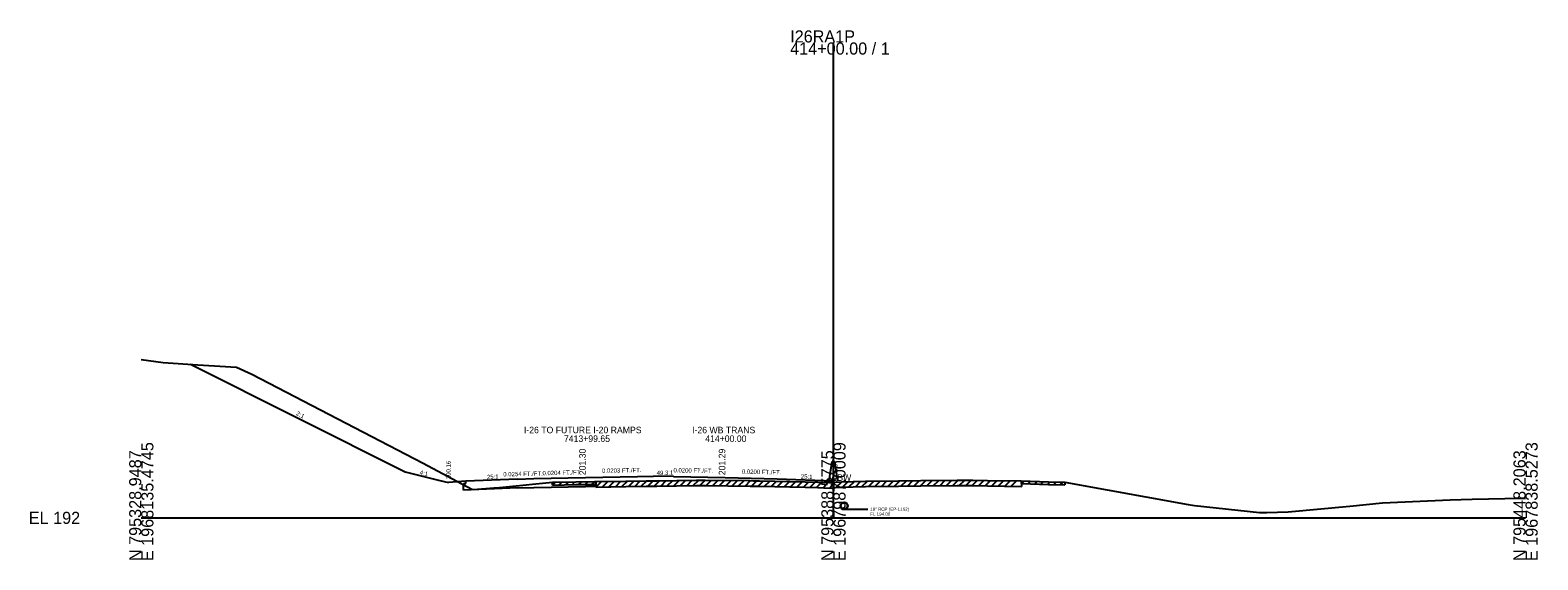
# Model space of a CAD drawing. Extents: x -44 to 4323, y -10 to 9601.
# Drawn here: x -25.7 to 322.8, y 8490.3 to 8612.7 of the extents above; entities that cross this region are included whole.
import ezdxf

# ---------------------------------------------------------------- set-up
doc = ezdxf.new("R2010")
doc.units = 0
for name, color, linetype in [('1', 7, 'Continuous'), ('DateStamp', 7, 'Continuous'), ('NotForConst', 7, 'Continuous'), ('QCQA', 7, 'Continuous'), ('RD_SHT_Bndy', 7, 'Continuous'), ('RD_SHT_Iplotshp', 7, 'Continuous'), ('RD_SHT_TX', 7, 'Continuous'), ('RD_TX_Misc1', 7, 'Continuous'), ('RD_XS_ExGround', 7, 'Continuous'), ('RD_XS_Misc_Line', 7, 'Continuous'), ('RD_XS_Pave', 7, 'Continuous'), ('RD_XS_PaveShd', 7, 'Continuous'), ('RD_XS_Pipe', 7, 'Continuous'), ('RD_XS_TX_Elev_PR', 7, 'Continuous'), ('RD_XS_TX_Profile', 7, 'Continuous'), ('RD_XS_TX_ShdSlope', 7, 'Continuous'), ('RD_XS_TX_Slope', 7, 'Continuous'), ('seal', 7, 'Continuous'), ('TR SN EXTRUDED PANEL SIGNS - GROUND MOUNTED', 7, 'Continuous')]:
    doc.layers.add(name, color=color, linetype=linetype)

msp = doc.modelspace()

# ---------------------------------------------------------------- linework, layer by layer
at = {"layer": 'DateStamp'}
msp.add_lwpolyline([(0, 8536.6), (5.07, 8535.9), (13.06, 8535.36), (22, 8534.83), (25.55, 8533.16), (65.15, 8512.65), (76.4, 8506.64), (76.79, 8506.54), (81.49, 8506.92), (82.06, 8506.96), (84.32, 8507.18), (95.09, 8508.22), (100.47, 8508.3), (104.77, 8508.37), (112.01, 8508.48), (116.68, 8508.56), (119.15, 8508.59), (128.37, 8508.7), (130.34, 8508.71), (140.72, 8508.6), (141.56, 8508.59), (142.89, 8508.56), (153.47, 8508.35), (156.37, 8508.25), (159.12, 8508.14), (160, 8508.2), (160.47, 8508.23), (161.85, 8508.33), (164.57, 8508.41), (167.42, 8508.48), (175.03, 8508.56), (180.19, 8508.63), (188.59, 8508.69), (192.22, 8508.72), (195.62, 8508.65), (203.37, 8508.52), (209.7, 8508.36), (213.46, 8508.27), (242.01, 8503.1), (242.98, 8502.93), (243.47, 8502.86), (258.51, 8501.23), (260.16, 8501.27), (265.13, 8501.43), (279.36, 8502.68), (286.9, 8503.49), (302.57, 8504.16), (307.63, 8504.33), (318.98, 8504.54), (320, 8504.54)], dxfattribs=at)
at = {"layer": 'NotForConst'}
for p, q in [((95.09, 8507.59), (95.73, 8508.23)), ((96.59, 8507.62), (97.23, 8508.25)), ((98.09, 8507.64), (98.73, 8508.27)), ((99.59, 8507.66), (100.23, 8508.3)), ((101.09, 8507.69), (101.73, 8508.32)), ((102.59, 8507.71), (103.23, 8508.34)), ((104.09, 8507.73), (104.73, 8508.36)), ((105.09, 8507.12), (106.36, 8508.39)), ((106.59, 8507.14), (107.86, 8508.41)), ((108.09, 8507.17), (109.36, 8508.44)), ((109.59, 8507.19), (110.86, 8508.46)), ((111.09, 8507.21), (112.36, 8508.49)), ((112.59, 8507.24), (113.86, 8508.51)), ((114.09, 8507.26), (115.36, 8508.54)), ((115.59, 8507.29), (116.86, 8508.56)), ((117.09, 8507.31), (118.36, 8508.58)), ((118.59, 8507.33), (119.86, 8508.6)), ((120.09, 8507.35), (121.36, 8508.62)), ((121.59, 8507.37), (122.86, 8508.63)), ((123.09, 8507.39), (124.36, 8508.65)), ((124.59, 8507.4), (125.86, 8508.67)), ((126.09, 8507.42), (127.36, 8508.69)), ((127.59, 8507.44), (128.86, 8508.7)), ((129.09, 8507.45), (130.35, 8508.71)), ((130.59, 8507.46), (131.83, 8508.7)), ((132.09, 8507.44), (133.33, 8508.68)), ((133.59, 8507.43), (134.83, 8508.66)), ((135.09, 8507.41), (136.33, 8508.65)), ((136.59, 8507.39), (137.83, 8508.63)), ((138.09, 8507.38), (139.33, 8508.61)), ((139.59, 8507.36), (140.83, 8508.6)), ((141.09, 8507.34), (142.32, 8508.57)), ((142.59, 8507.32), (143.82, 8508.54)), ((144.09, 8507.29), (145.32, 8508.51)), ((145.59, 8507.26), (146.82, 8508.48)), ((147.09, 8507.23), (148.32, 8508.45)), ((148.59, 8507.2), (149.82, 8508.42)), ((150.09, 8507.17), (151.32, 8508.4)), ((151.59, 8507.14), (152.82, 8508.37)), ((153.09, 8507.11), (154.31, 8508.32)), ((154.59, 8507.06), (155.8, 8508.27)), ((156.09, 8507.01), (157.3, 8508.21)), ((157.59, 8506.95), (158.8, 8508.16)), ((159.09, 8506.89), (160.43, 8508.23)), ((160.59, 8506.99), (161.94, 8508.34)), ((162.09, 8507.09), (163.38, 8508.38)), ((163.59, 8507.13), (164.88, 8508.42)), ((165.09, 8507.17), (166.37, 8508.45)), ((166.59, 8507.21), (167.87, 8508.48)), ((168.09, 8507.24), (169.36, 8508.5)), ((169.59, 8507.25), (170.86, 8508.52)), ((171.09, 8507.27), (172.36, 8508.53)), ((172.59, 8507.28), (173.86, 8508.55)), ((174.09, 8507.3), (175.36, 8508.57)), ((175.59, 8507.32), (176.86, 8508.58)), ((177.09, 8507.34), (178.36, 8508.6)), ((178.59, 8507.36), (179.86, 8508.62)), ((180.09, 8507.38), (181.35, 8508.64)), ((181.59, 8507.39), (182.85, 8508.65)), ((183.09, 8507.4), (184.35, 8508.66)), ((184.59, 8507.41), (185.85, 8508.67)), ((186.09, 8507.42), (187.35, 8508.68)), ((187.59, 8507.44), (188.85, 8508.7)), ((189.09, 8507.45), (190.35, 8508.7)), ((190.59, 8507.46), (191.85, 8508.71)), ((192.09, 8507.46), (193.32, 8508.69)), ((193.59, 8507.44), (194.82, 8508.67)), ((195.09, 8507.41), (196.32, 8508.64)), ((196.59, 8507.39), (197.82, 8508.61)), ((198.09, 8507.36), (199.32, 8508.59)), ((199.59, 8507.34), (200.82, 8508.56)), ((201.09, 8507.31), (202.32, 8508.54)), ((203.46, 8507.9), (204.07, 8508.5)), ((204.96, 8507.86), (205.57, 8508.47)), ((206.46, 8507.82), (207.07, 8508.43)), ((207.96, 8507.78), (208.57, 8508.39)), ((209.46, 8507.74), (210.07, 8508.35)), ((210.96, 8507.71), (211.57, 8508.32)), ((212.46, 8507.67), (213.07, 8508.28))]:
    msp.add_line(p, q, dxfattribs=at)
at = {"layer": 'QCQA'}
for p, q in [((105.09, 8508.37), (112.01, 8508.48)), ((105.09, 8508.37), (105.09, 8507.31)), ((112.01, 8508.48), (116.68, 8508.56)), ((116.68, 8508.56), (119.15, 8508.59)), ((119.15, 8508.59), (128.37, 8508.7)), ((128.37, 8508.7), (130.34, 8508.71)), ((130.34, 8508.71), (140.72, 8508.6)), ((140.72, 8508.6), (141.56, 8508.59)), ((141.56, 8508.59), (142.89, 8508.56)), ((142.89, 8508.56), (153.47, 8508.35)), ((153.47, 8508.35), (156.37, 8508.25)), ((156.37, 8508.25), (159.12, 8508.14)), ((159.12, 8508.14), (160, 8508.2))]:
    msp.add_line(p, q, dxfattribs=at)
at = {"layer": 'RD_SHT_Bndy'}
for p, q in [((160, 8500), (160, 8609.81)), ((0, 8500), (160, 8500)), ((160, 8500), (320, 8500))]:
    msp.add_line(p, q, dxfattribs=at)
at = {"layer": 'RD_SHT_Iplotshp'}
for p, q in [((95.09, 8507.59), (95.09, 8508.22)), ((100.47, 8507.68), (104.77, 8507.74)), ((104.77, 8507.74), (105.09, 8507.75)), ((105.09, 8507.12), (105.09, 8508.37)), ((105.09, 8508.37), (105.09, 8507.75)), ((203.46, 8508.52), (203.46, 8507.27)), ((203.46, 8507.9), (203.46, 8508.52)), ((203.46, 8507.9), (209.7, 8507.74)), ((209.7, 8507.74), (213.46, 8507.65)), ((213.46, 8508.27), (213.46, 8507.65)), ((95.09, 8507.59), (100.47, 8507.68)), ((105.09, 8507.12), (112.01, 8507.23)), ((112.01, 8507.23), (116.68, 8507.31)), ((116.68, 8507.31), (119.15, 8507.34)), ((119.15, 8507.34), (128.37, 8507.45)), ((128.37, 8507.45), (130.34, 8507.46)), ((130.34, 8507.46), (140.72, 8507.35)), ((140.72, 8507.35), (141.56, 8507.34)), ((141.56, 8507.34), (142.89, 8507.31)), ((142.89, 8507.31), (153.47, 8507.1)), ((153.47, 8507.1), (156.37, 8507)), ((156.37, 8507), (159.12, 8506.89)), ((159.12, 8506.89), (160, 8506.95)), ((160, 8506.95), (160.47, 8506.98)), ((160.47, 8506.98), (161.85, 8507.08)), ((161.85, 8507.08), (164.57, 8507.16)), ((164.57, 8507.16), (167.42, 8507.23)), ((167.42, 8507.23), (175.03, 8507.31)), ((175.03, 8507.31), (180.19, 8507.38)), ((180.19, 8507.38), (188.59, 8507.44)), ((188.59, 8507.44), (192.22, 8507.47)), ((192.22, 8507.47), (195.62, 8507.4)), ((195.62, 8507.4), (203.37, 8507.27)), ((203.37, 8507.27), (203.46, 8507.27))]:
    msp.add_line(p, q, dxfattribs=at)
at = {"layer": 'RD_TX_Misc1'}
for p in [(69, 8508.66), (73, 8508.32)]:
    msp.add_line(p, (71, 8508.16), dxfattribs=at)
at = {"layer": 'RD_XS_Misc_Line'}
for p, q in [((74.5, 8507.9), (75, 8507.92)), ((74.5, 8506.42), (74.5, 8507.9)), ((75, 8507.92), (75, 8508.48)), ((87, 8506.92), (74.5, 8506.42)), ((87, 8506.92), (90.72, 8507.02)), ((90.72, 8507.02), (102.72, 8507.26)), ((102.72, 8507.26), (105.09, 8507.31))]:
    msp.add_line(p, q, dxfattribs=at)
at = {"layer": 'RD_XS_Pave'}
for p, q in [((11.37, 8535.47), (61, 8510.66)), ((61, 8510.66), (69, 8508.66))]:
    msp.add_line(p, q, dxfattribs=at)
at = {"layer": 'RD_XS_PaveShd'}
msp.add_line((75, 8508.48), (73, 8508.32), dxfattribs=at)
at = {"layer": 'RD_XS_Pipe'}
msp.add_line((162.99, 8502), (167.99, 8502), dxfattribs=at)
for radius in [0.85, 0.75]:
    msp.add_circle((162.49, 8502.75), radius, dxfattribs=at)
at = {"layer": 'RD_XS_TX_Elev_PR'}
for p, q in [((87, 8508.96), (75, 8508.48)), ((114.73, 8509.54), (118.38, 8509.62)), ((123, 8509.53), (118.38, 8509.62)), ((147, 8509.05), (160, 8508.53)), ((160, 8508.53), (160, 8508.2))]:
    msp.add_line(p, q, dxfattribs=at)
at = {"layer": 'RD_XS_TX_ShdSlope'}
for p, q in [((159, 8508.55), (159.67, 8513.03)), ((160, 8513.03), (159.67, 8513.03)), ((160, 8513.03), (160.33, 8513.03)), ((161, 8508.55), (160.33, 8513.03))]:
    msp.add_line(p, q, dxfattribs=at)
at = {"layer": 'RD_XS_TX_Slope'}
for p, q in [((87, 8508.96), (90.72, 8509.06)), ((90.72, 8509.06), (102.72, 8509.3)), ((102.72, 8509.3), (114.73, 8509.54)), ((123, 8509.53), (135, 8509.29)), ((135, 8509.29), (147, 8509.05))]:
    msp.add_line(p, q, dxfattribs=at)

# ---------------------------------------------------------------- texts
at = {"layer": '1'}
for s, p in [('I-26 TO FUTURE I-20 RAMPS', (88.45, 8519.55)), ('7413+99.65', (97.7, 8517.55)), ('I-26 WB TRANS', (127.33, 8519.54)), ('414+00.00', (130.36, 8517.54))]:
    msp.add_text(s, height=1.5, dxfattribs=at).set_placement(p)
at = {"layer": 'RD_SHT_Bndy'}
for s, p in [('I26RA1P', (150, 8609.81)), ('414+00.00 / 1', (150, 8607.01)), ('EL 192', (-26, 8498.6))]:
    msp.add_text(s, height=2.8, dxfattribs=at).set_placement(p)
for s, p in [('N 795328.9487', (0, 8490)), ('E 1968135.4745', (2.8, 8490)), ('N 795388.5775', (160, 8490)), ('E 1967987.0009', (162.8, 8490)), ('N 795448.2063', (320, 8490)), ('E 1967838.5273', (322.8, 8490))]:
    msp.add_text(s, height=2.8, rotation=90, dxfattribs=at).set_placement(p)
at = {"layer": 'RD_SHT_TX'}
msp.add_text('200.20', height=1, rotation=90, dxfattribs=at).set_placement((161, 8508.2))
at = {"layer": 'RD_XS_ExGround'}
for s, rotation, p in [('25:1', 2.29, (79.93, 8508.93)), ('49.3:1', 1.1612, (119.15, 8509.88)), ('25:1', 357.7094, (152.46, 8509.08))]:
    msp.add_text(s, height=1, rotation=rotation, dxfattribs=at).set_placement(p)
at = {"layer": 'RD_XS_Pipe'}
for s, p in [('18" RCP (EP-1162)', (168.49, 8501.63)), ('FL 194.00', (168.49, 8500.5))]:
    msp.add_text(s, height=0.75, dxfattribs=at).set_placement(p)
at = {"layer": 'RD_XS_TX_Profile'}
msp.add_text('WBW', height=1.5, dxfattribs=at).set_placement((159, 8508.55))
at = {"layer": 'seal'}
for s, p in [(' 201.30', (102.72, 8509.3)), (' 201.29', (135, 8509.29))]:
    msp.add_text(s, height=1.5, rotation=90, dxfattribs=at).set_placement(p)
at = {"layer": 'TR SN EXTRUDED PANEL SIGNS - GROUND MOUNTED'}
for s, rotation, p in [('2:1', 333.4349, (35.69, 8523.81)), ('200.16', 90, (71.49, 8508.94)), ('0.0203 FT./FT.', 1.1612, (106.51, 8510.38)), ('0.0200 FT./FT.', 358.8542, (123.02, 8510.52)), ('0.0200 FT./FT.', 358.8542, (138.83, 8510.21)), ('4:1', 345.9638, (64.28, 8510.07)), ('0.0254 FT./FT.', 1.4542, (83.69, 8509.55)), ('0.0204 FT./FT.', 1.1676, (92.75, 8509.83))]:
    msp.add_text(s, height=1, rotation=rotation, dxfattribs=at).set_placement(p)

doc.saveas('drawing.dxf')
